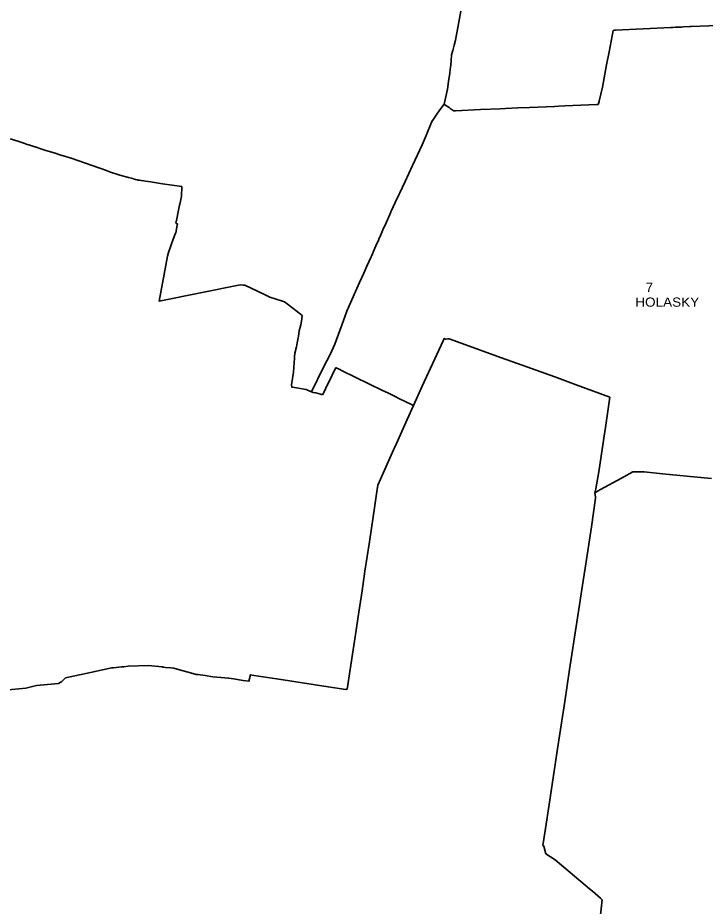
# Model space of a CAD drawing. Extents: x -610940 to -588976, y -1170376 to -1149800.
# Drawn here: x -598026 to -596159, y -1167918 to -1165505 of the extents above; entities that cross this region are included whole.
import ezdxf

# ---------------------------------------------------------------- set-up
doc = ezdxf.new("R2010")
doc.units = 0
doc.header["$LTSCALE"] = 10
doc.layers.add('54', color=7, linetype='Continuous', lineweight=35)
doc.layers.add('55', color=7, linetype='Continuous')
doc.layers.add('56', color=7, linetype='Continuous')

msp = doc.modelspace()

# ---------------------------------------------------------------- linework, layer by layer
at = {"layer": '54'}
for p, q in [((-596419.88, -1165597.52), (-596409.22, -1165539.43)), ((-596404.16, -1165539.07), (-596404.85, -1165539.11)), ((-596404.16, -1165539.07), (-596402.1, -1165538.97)), ((-596402.1, -1165538.97), (-596251.79, -1165531.44)), ((-596251.79, -1165531.44), (-596246.76, -1165531.27)), ((-596246.76, -1165531.27), (-596239.15, -1165531.04)), ((-596223.34, -1165530.37), (-596239.15, -1165531.04)), ((-596223.34, -1165530.37), (-596218.13, -1165530.05)), ((-596218.13, -1165530.05), (-596200.62, -1165529.14)), ((-596200.62, -1165529.14), (-596196.67, -1165528.73)), ((-596196.67, -1165528.73), (-596097.25, -1165525.08)), ((-596426.6, -1165633.41), (-596419.88, -1165597.52)), ((-596438.04, -1165693.82), (-596426.6, -1165633.41)), ((-596438.04, -1165693.82), (-596446.86, -1165731.47)), ((-596449.43, -1165740.95), (-596447.23, -1165733.04)), ((-596447.23, -1165733.04), (-596446.86, -1165731.47)), ((-596868.16, -1165739.79), (-596865.79, -1165741.45)), ((-596854.51, -1165749.35), (-596865.79, -1165741.45)), ((-596854.51, -1165749.35), (-596851.4, -1165751.5)), ((-596851.4, -1165751.5), (-596843.41, -1165757)), ((-596843.41, -1165757), (-596841.98, -1165757.99)), ((-596841.98, -1165757.99), (-596836.77, -1165757.75)), ((-596836.77, -1165757.75), (-596769.15, -1165754.61)), ((-596769.15, -1165754.61), (-596715.54, -1165752.12)), ((-596715.54, -1165752.12), (-596701.34, -1165751.51)), ((-596701.34, -1165751.51), (-596667.9, -1165750.05)), ((-596667.9, -1165750.05), (-596636.32, -1165748.67)), ((-596636.32, -1165748.67), (-596613.05, -1165747.68)), ((-596613.05, -1165747.68), (-596567.79, -1165745.77)), ((-596567.79, -1165745.77), (-596557.29, -1165745.33)), ((-596557.29, -1165745.33), (-596539.66, -1165744.58)), ((-596453.22, -1165740.92), (-596539.66, -1165744.58)), ((-596449.43, -1165740.95), (-596453.22, -1165740.92)), ((-596988.32, -1165981.05), (-596973.76, -1165949.7)), ((-597000.7, -1166007.08), (-596989.92, -1165984.49)), ((-596989.92, -1165984.49), (-596988.32, -1165981.05)), ((-597011.65, -1166030.05), (-597000.7, -1166007.08)), ((-597025.85, -1166062.39), (-597015.65, -1166039.15)), ((-597015.65, -1166039.15), (-597011.65, -1166030.05)), ((-597034.15, -1166081.31), (-597025.85, -1166062.39)), ((-597042.02, -1166099.24), (-597034.15, -1166081.31)), ((-597053.15, -1166124.35), (-597052.28, -1166122.38)), ((-597052.28, -1166122.38), (-597046.74, -1166109.92)), ((-597065.67, -1166152.5), (-597053.15, -1166124.35)), ((-597071.94, -1166166.61), (-597066.52, -1166154.43)), ((-597066.52, -1166154.43), (-597065.67, -1166152.5)), ((-597086.38, -1166198.8), (-597080.87, -1166186.38)), ((-597097.84, -1166224.62), (-597086.38, -1166198.8)), ((-597141.32, -1166327.23), (-597132.02, -1166301.83)), ((-596711.74, -1166428.71), (-596655.95, -1166448.37)), ((-597162.6, -1166455.3), (-597172.54, -1166475.8)), ((-597190.47, -1166513.01), (-597172.54, -1166475.8)), ((-596417.46, -1166535.91), (-596509.09, -1166502.28)), ((-597216.9, -1166524.36), (-597223.88, -1166522.68)), ((-597203.96, -1166527.47), (-597216.9, -1166524.36)), ((-597197.99, -1166528.91), (-597203.96, -1166527.47)), ((-597197.99, -1166528.91), (-597196.84, -1166526.48)), ((-597196.84, -1166526.48), (-597190.47, -1166513.01)), ((-597021.33, -1166524.1), (-597035.43, -1166517.22)), ((-597006.17, -1166531.5), (-597021.33, -1166524.1)), ((-597003.1, -1166533), (-597006.17, -1166531.5)), ((-596989.15, -1166539.81), (-597003.1, -1166533)), ((-596974.14, -1166547.14), (-596989.15, -1166539.81)), ((-596974.14, -1166547.14), (-596955.28, -1166556.35)), ((-596954.15, -1166556.99), (-596955.28, -1166556.35)), ((-596954.15, -1166556.99), (-596951.16, -1166558.63)), ((-596417.46, -1166535.91), (-596430.75, -1166624.68)), ((-596447.98, -1166738.86), (-596456.28, -1166784.64)), ((-596354.76, -1166738.36), (-596351.89, -1166738.55)), ((-596456.28, -1166784.64), (-596458.19, -1166795.2))]:
    msp.add_line(p, q, dxfattribs=at)
for points in [[(-596868.16, -1165739.79), (-596858.93, -1165698.74), (-596856.01, -1165677.98), (-596852.77, -1165655.83), (-596851.51, -1165644.6), (-596850.07, -1165633.81), (-596849.15, -1165622.27), (-596848.14, -1165606.08), (-596844.75, -1165593.81), (-596840.78, -1165579.41), (-596837.19, -1165566.42), (-596822.46, -1165487.36)], [(-596409.22, -1165539.43), (-596404.91, -1165539.11), (-596404.85, -1165539.11)], [(-596973.76, -1165949.7), (-596953.58, -1165906.26), (-596927.71, -1165850.76), (-596916.82, -1165824.53), (-596901.07, -1165786.64), (-596897.18, -1165780.21), (-596889.81, -1165769.7), (-596879.83, -1165755.48), (-596868.16, -1165739.79)], [(-597937.27, -1165869.15), (-597949.7, -1165865.26), (-597963.57, -1165860.92), (-597978.75, -1165856.17), (-597980.09, -1165855.73), (-597987.85, -1165853.18), (-597996.19, -1165850.43), (-598000.56, -1165848.99), (-598009.76, -1165845.96), (-598023.76, -1165841.36), (-598025.88, -1165840.66), (-598047.21, -1165833.64)], [(-597596.57, -1166062.69), (-597595.59, -1166057.96), (-597595.31, -1166056.6), (-597595.12, -1166055.67), (-597593.32, -1166046.89), (-597591.25, -1166036.84), (-597589.32, -1166027.43), (-597586.62, -1166014.3), (-597586.07, -1166011.55), (-597581.72, -1165990.48), (-597580.69, -1165963.44), (-597632.7, -1165955.84), (-597660.24, -1165951.81), (-597664.86, -1165951.13), (-597679.18, -1165949.04), (-597683.67, -1165948.29), (-597691, -1165947.08), (-597695.33, -1165946.51), (-597695.66, -1165946.53), (-597699.79, -1165945.87), (-597700.1, -1165945.79), (-597701.39, -1165945.45), (-597702.54, -1165945.15), (-597706.58, -1165944.09), (-597712.77, -1165942.47), (-597713.34, -1165942.32), (-597713.98, -1165942.15), (-597717.47, -1165941.26), (-597725.68, -1165939.08), (-597735.2, -1165936.59), (-597748.73, -1165932.84), (-597776.68, -1165923.31), (-597785.08, -1165920.22), (-597881.48, -1165886.69), (-597905.58, -1165879.55), (-597906.87, -1165879.16), (-597917.36, -1165875.71), (-597919.44, -1165875.03), (-597927.24, -1165872.46), (-597937.27, -1165869.15)], [(-597228.29, -1166521.62), (-597231.21, -1166520.24), (-597242.83, -1166515.15), (-597274.5, -1166509.88), (-597281.31, -1166508.75), (-597282.57, -1166502.27), (-597277.06, -1166467.57), (-597274.37, -1166430.21), (-597274.25, -1166429.49), (-597274.54, -1166425.75), (-597273.92, -1166415.93), (-597269.46, -1166399.43), (-597268.61, -1166393.11), (-597267.44, -1166388.55), (-597264.66, -1166374.43), (-597263.39, -1166370.94), (-597261.9, -1166355.5), (-597257.6, -1166339.24), (-597255.01, -1166323.86), (-597253.28, -1166314.29), (-597262.52, -1166306.99), (-597290.82, -1166284.61), (-597294.23, -1166282.09), (-597301.45, -1166276.43), (-597306.82, -1166274.73), (-597341.19, -1166263.82), (-597353.89, -1166257.91), (-597409.19, -1166231.9), (-597414.07, -1166231.44), (-597422.03, -1166230.7), (-597642.09, -1166275.01), (-597619.82, -1166152.39), (-597616.58, -1166142.67), (-597604.45, -1166106.3), (-597597.34, -1166090.54), (-597597.18, -1166089.92), (-597592.86, -1166067.84), (-597592.19, -1166064.46), (-597593.68, -1166063.86), (-597596.57, -1166062.69)], [(-597046.74, -1166109.92), (-597044.23, -1166104.27), (-597042.02, -1166099.24)], [(-597080.87, -1166186.38), (-597077.86, -1166179.84), (-597071.94, -1166166.61)], [(-597132.02, -1166301.83), (-597125.88, -1166287.78), (-597097.84, -1166224.62)], [(-597223.88, -1166522.68), (-597228.29, -1166521.62), (-597195.57, -1166453.91), (-597177.88, -1166419.86), (-597165.05, -1166392.09), (-597141.32, -1166327.23)], [(-596870.89, -1166382.64), (-596927.34, -1166506.12), (-596951.16, -1166558.63)], [(-596711.74, -1166428.71), (-596854.31, -1166377.32), (-596857.33, -1166376.94), (-596863.88, -1166378.17), (-596868.04, -1166376.52), (-596870.89, -1166382.64)], [(-597151.11, -1166460.62), (-597161.01, -1166456.04), (-597162.6, -1166455.3)], [(-597035.43, -1166517.22), (-597146.7, -1166462.91), (-597151.11, -1166460.62)], [(-596509.09, -1166502.28), (-596567.42, -1166480.87), (-596579.87, -1166476.29), (-596655.95, -1166448.37)], [(-596951.16, -1166558.63), (-596968.36, -1166596.68), (-596997.53, -1166661.3), (-597003.16, -1166673.76), (-597004.4, -1166676.8), (-597047.78, -1166774.3), (-597051.39, -1166798.65), (-597056.29, -1166829.86), (-597070.88, -1166928.89), (-597083.07, -1167007.91), (-597090.98, -1167061.46), (-597101.92, -1167131.35), (-597107.41, -1167168.42), (-597131.73, -1167328.89), (-597134.7, -1167329.89), (-597182.96, -1167322.61), (-597316.77, -1167301.69), (-597390.42, -1167290.41), (-597394.08, -1167289.85), (-597398.18, -1167307.16), (-597413.54, -1167304.95), (-597440.01, -1167301.15), (-597452.51, -1167299.36), (-597454.24, -1167299.14), (-597464.19, -1167298.16), (-597474.81, -1167297.12), (-597496.07, -1167294.97), (-597517.18, -1167292.06), (-597537.32, -1167289.29), (-597541.86, -1167288.67), (-597557, -1167284.57), (-597566.72, -1167281.94), (-597576.55, -1167279.28), (-597586.47, -1167276.6), (-597596.12, -1167273.99), (-597602.73, -1167272.2), (-597610.68, -1167271.09), (-597624.83, -1167269.56), (-597629.19, -1167269.04), (-597630.5, -1167268.95)], [(-596447.98, -1166738.86), (-596431.48, -1166629.36), (-596430.75, -1166624.68)], [(-596354.76, -1166738.36), (-596355.09, -1166738.54), (-596386.25, -1166755.68), (-596443.48, -1166786.91)], [(-596274.54, -1166744.22), (-596324.53, -1166738.83), (-596345.98, -1166738.94), (-596347.51, -1166738.84), (-596351.89, -1166738.55)], [(-596274.54, -1166744.22), (-596161.73, -1166754.59), (-596141.49, -1166756.45)], [(-596438.3, -1167901.32), (-596443.25, -1167896.85), (-596465.37, -1167877.39), (-596472.85, -1167871.17), (-596566.51, -1167792.66), (-596591.57, -1167775.74), (-596597.29, -1167754.97), (-596599.56, -1167753.46), (-596592.66, -1167707.14), (-596583, -1167641.8), (-596559.83, -1167490.66), (-596540.36, -1167361.91), (-596527.35, -1167275.86), (-596505.87, -1167135.19), (-596490.53, -1167034.68), (-596484.64, -1166999.86), (-596468.09, -1166887.63), (-596456.59, -1166810.46), (-596456.91, -1166807.09), (-596458.19, -1166795.2), (-596449.51, -1166790.31), (-596443.48, -1166786.91)], [(-597630.5, -1167268.95), (-597632.12, -1167268.73), (-597633.95, -1167268.57), (-597671.1, -1167264.45), (-597725.94, -1167266.78), (-597738.5, -1167268.35), (-597738.83, -1167268.35), (-597744.62, -1167268.33), (-597766.02, -1167270.54), (-597771.3, -1167270.63), (-597816.16, -1167280.44), (-597896.89, -1167298.1), (-597901.78, -1167303.28), (-597906.41, -1167308.18), (-597915.77, -1167313.8), (-597975.55, -1167319.26), (-598004.63, -1167326.28), (-598100.53, -1167335.31)], [(-596899.13, -1167965.68), (-596874.84, -1167968.91), (-596731.82, -1167985.8), (-596657.06, -1167994.63), (-596616.91, -1167999.7), (-596613.94, -1168000.07), (-596455.07, -1168019.2), (-596451.22, -1168016.87), (-596451.11, -1168011.91), (-596449.77, -1167999.83), (-596438.3, -1167901.32)]]:
    msp.add_lwpolyline(points, dxfattribs=at)

# ---------------------------------------------------------------- texts
at = {"layer": '55', "width": 1.1}
msp.add_text('HOLASKY ', height=25, dxfattribs=at).set_placement((-596348.74, -1166290.03))
at = {"layer": '56', "width": 1.1}
msp.add_text('7 ', height=25, dxfattribs=at).set_placement((-596320.66, -1166249.62))

doc.saveas('drawing.dxf')
